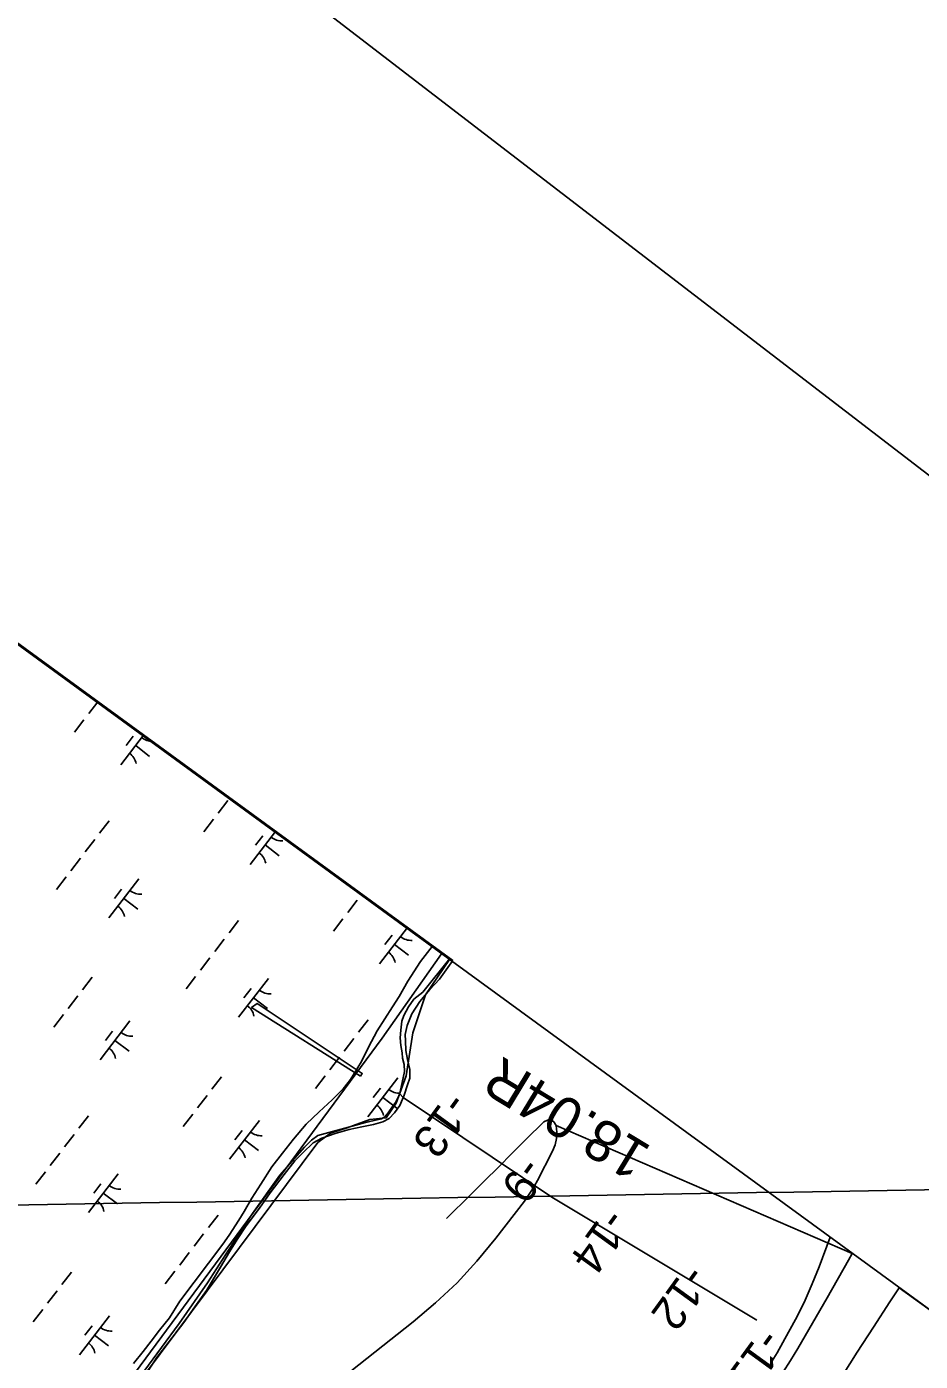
# Model space of a CAD drawing. Extents: x 3879599 to 3900814, y 146526 to 168888.
# Drawn here: x 3894566 to 3895476, y 162574 to 163934 of the extents above; entities that cross this region are included whole.
import ezdxf

# ---------------------------------------------------------------- set-up
doc = ezdxf.new("R2010")
doc.units = 0
for name, color, linetype in [('V-ANNO-SYMB', 7, 'Continuous'), ('V-CHAN-DOCK', 7, 'Continuous'), ('V-GRID-FRAM', 7, 'Continuous'), ('V-GRID-MAJR', 7, 'Continuous'), ('V-LEVE-TOET', 7, 'Continuous'), ('V-RIVR-EDGE', 7, 'Continuous'), ('V-RIVR-JETY', 7, 'Continuous'), ('V-RIVR-RANG', 7, 'Continuous'), ('V-RRAP-FSHR', 7, 'Continuous'), ('V-STRM-FMON', 7, 'Continuous'), ('V-TOPO-DPTH', 7, 'Continuous'), ('V-TOPO-MINR', 7, 'Continuous'), ('V-WETL-SWMP', 7, 'Continuous')]:
    doc.layers.add(name, color=color, linetype=linetype)

msp = doc.modelspace()

# ---------------------------------------------------------------- linework, layer by layer
at = {"layer": 'V-ANNO-SYMB'}
msp.add_lwpolyline([(3890411.2, 167376), (3880331.9, 154259.9), (3889417.3, 147278), (3899496.7, 160394.1), (3890411.2, 167376)], dxfattribs=at)
at = {"layer": 'V-CHAN-DOCK'}
msp.add_lwpolyline([(3894905.9, 162864.7), (3894795.1, 162934.6), (3894800.7, 162938.7), (3894907.9, 162867.4), (3894907.9, 162867.4)], close=True, dxfattribs=at)
at = {"layer": 'V-GRID-FRAM'}
msp.add_lwpolyline([(3898776.6, 160226.4), (3889730.7, 148455.2), (3882888.9, 153284.4), (3891901.5, 165241.3), (3898776.6, 160226.4)], dxfattribs=at)
at = {"layer": 'V-GRID-MAJR'}
msp.add_spline([(3889435.5, 162648.2), (3893979, 162723.9), (3896411.9, 162764.6)], degree=3, dxfattribs=at)
at = {"layer": 'V-LEVE-TOET'}
msp.add_lwpolyline([(3894946.2, 162846.8), (3894949.5, 162843.2), (3895101.1, 162741.4), (3895310, 162616.3)], dxfattribs=at)
at = {"layer": 'V-RIVR-EDGE'}
msp.add_lwpolyline([(3894996.8, 162983.5), (3894972.2, 162947.8), (3894959.2, 162908.8), (3894952.7, 162865.1), (3894942.5, 162837.3), (3894932.3, 162822.4), (3894915.5, 162820.5), (3894892.3, 162812.2), (3894875.6, 162806.6), (3894862.6, 162797.3), (3894686, 162560.4), (3894503, 162313.2), (3894441.7, 162241.6), (3894369.2, 162130.1), (3894334.8, 162095.7), (3894315.3, 162075.3), (3893894.3, 161523.4), (3893644.4, 161210.2), (3893630.5, 161202.8), (3893449.3, 161162.8), (3893262.5, 161121.9), (3892618.5, 160989.1), (3892386.2, 160942.6)], dxfattribs=at)
at = {"layer": 'V-RIVR-JETY'}
for points in [[(3894979.6, 162997.5), (3894979.1, 162996.9), (3894967.3, 162981.5), (3894954.4, 162961.7), (3894945.5, 162945.9), (3894938.7, 162935.5), (3894923.1, 162911.1), (3894914.3, 162894.3), (3894907.2, 162879.8), (3894896, 162861.4), (3894888.5, 162852), (3894877.3, 162840.6), (3894864.1, 162828.6), (3894850.6, 162815.9), (3894837.7, 162800.5), (3894826.6, 162786.4), (3894815.7, 162772.3), (3894804.5, 162754.9), (3894795.4, 162740.4), (3894787.5, 162727), (3894782.1, 162718), (3894772.3, 162702.9), (3894765.8, 162693.8), (3894722.1, 162635.5), (3894711.3, 162618.7), (3894701.1, 162606), (3894692.6, 162594.9), (3894684.5, 162584.2), (3894674.7, 162572.1)], [(3894997.1, 162984.7), (3894969.4, 162950.3), (3894960.5, 162943.1), (3894954.8, 162935.4), (3894950.3, 162926.5), (3894948.2, 162920.9), (3894947, 162911.5), (3894946.5, 162903.9), (3894947.3, 162896.2), (3894948.5, 162888.5), (3894948.8, 162883.2), (3894950.4, 162876.7), (3894950.8, 162869.4), (3894946.6, 162848.8), (3894946.2, 162846.8), (3894942.1, 162838.3), (3894938.8, 162833.8), (3894934.4, 162827.4), (3894930.7, 162823.4), (3894927.4, 162821.4), (3894915.7, 162818.6), (3894905.1, 162815.8), (3894862.6, 162804.3), (3894856.1, 162799.5), (3894853.2, 162796.6), (3894849.1, 162792.6), (3894823.9, 162764), (3894796.1, 162724.9), (3894771.7, 162687.7), (3894750, 162654.3), (3894721.4, 162612.7), (3894685.2, 162563.9)]]:
    msp.add_lwpolyline(points, dxfattribs=at)
at = {"layer": 'V-RRAP-FSHR'}
msp.add_lwpolyline([(3894988.6, 162989.5), (3894928.1, 162903.5), (3894582.9, 162435.8), (3894412.9, 162213.5), (3894350.9, 162125.8), (3894296.7, 162068.7), (3894092.5, 161803.5), (3893724.5, 161331), (3893640.5, 161218.2), (3893416.1, 161165.6), (3892609.1, 161000)], dxfattribs=at)
at = {"layer": 'V-TOPO-DPTH'}
msp.add_line((3895669.6, 162492.7), (3895455, 162649.3), dxfattribs=at)
for points in [[(3894583.4, 161564.9), (3894255.7, 161739.6), (3894330.1, 161816), (3894779.1, 162471.7), (3894959.7, 162614.4), (3894982.6, 162633.9), (3895004.4, 162654.4), (3895024.6, 162676.5), (3895043.8, 162699.7), (3895073, 162737.6), (3895076.7, 162742.7), (3895080.1, 162747.8), (3895083.3, 162753.2), (3895086.4, 162758.6), (3895101.8, 162788.4), (3895104.3, 162794.7), (3895105.9, 162801.2), (3895106.1, 162807.8), (3895105.4, 162814.6), (3895407.1, 162684.2)], [(3895407.1, 162684.2), (3895403.3, 162677.4), (3895381.5, 162638.9), (3895351.7, 162587.4), (3895344.2, 162575), (3895336.4, 162562.9)], [(3895336.4, 162562.9), (3895344.2, 162575), (3895351.7, 162587.4), (3895381.5, 162638.9), (3895403.3, 162677.4), (3895407.1, 162684.2)], [(3895455, 162649.3), (3895445.3, 162634.8), (3895428.6, 162609.2), (3895412.1, 162583.5), (3895389.6, 162547.9)], [(3895455, 162649.3), (3895445.3, 162634.8), (3895428.6, 162609.2), (3895412.1, 162583.5), (3895389.6, 162547.9)]]:
    msp.add_lwpolyline(points, dxfattribs=at)
at = {"layer": 'V-TOPO-MINR'}
for points in [[(3894993.7, 162719.7), (3895018.3, 162744.2), (3895032.4, 162758.2), (3895046.5, 162772.2), (3895060.6, 162786.2), (3895074.6, 162800.2), (3895092.7, 162818.4), (3895096.7, 162820.1), (3895100.2, 162820.3), (3895103.1, 162818.2), (3895105.4, 162814.6), (3895106.1, 162807.8), (3895105.9, 162801.2), (3895104.3, 162794.7), (3895101.8, 162788.4), (3895086.4, 162758.6), (3895083.3, 162753.2), (3895080.1, 162747.8), (3895076.7, 162742.7), (3895073, 162737.6), (3895043.8, 162699.7), (3895024.6, 162676.5), (3895004.4, 162654.4), (3894982.6, 162633.9), (3894959.7, 162614.4), (3894779.1, 162471.7)], [(3895384.6, 162700.7), (3895373.2, 162670.5), (3895366.4, 162653.4), (3895359, 162636.6), (3895350.9, 162620.1), (3895342.2, 162603.9), (3895330.5, 162583), (3895327.2, 162577.4), (3895323.7, 162572)], [(3895407.1, 162684.2), (3895403.3, 162677.4), (3895381.5, 162638.9), (3895351.7, 162587.4), (3895344.2, 162575), (3895336.4, 162562.9)], [(3895455, 162649.3), (3895445.3, 162634.8), (3895428.6, 162609.2), (3895412.1, 162583.5), (3895389.6, 162547.9)]]:
    msp.add_lwpolyline(points, dxfattribs=at)
at = {"layer": 'V-WETL-SWMP'}
for p, q in [((3895000.1, 162982.5), (3893763.6, 163884.4)), ((3894638.5, 163246.3), (3894629.2, 163234.2)), ((3894624.3, 163227.8), (3894614.6, 163215.1)), ((3894685.1, 163212.3), (3894661.7, 163181.8)), ((3894674.5, 163211.1), (3894667.2, 163201.6)), ((3894677, 163201.6), (3894691.2, 163190.6)), ((3894770.8, 163145.5), (3894761.1, 163132.8)), ((3894650, 163124.9), (3894640.2, 163112.2)), ((3894756.2, 163126.5), (3894746.5, 163113.8)), ((3894819.6, 163114.2), (3894793.6, 163080.4)), ((3894806.4, 163109.7), (3894799.1, 163100.2)), ((3894635.4, 163105.8), (3894625.6, 163093.2)), ((3894808.9, 163100.3), (3894823.1, 163089.3)), ((3894620.7, 163086.8), (3894611, 163074.1)), ((3894606.1, 163067.8), (3894596.4, 163055.1)), ((3894680.3, 163065.8), (3894649.8, 163026.1)), ((3894662.6, 163055.4), (3894655.3, 163045.9)), ((3894665, 163045.9), (3894679.3, 163035)), ((3894902.7, 163044.1), (3894893, 163031.5)), ((3894888.1, 163025.1), (3894878.4, 163012.4)), ((3894781.9, 163023.5), (3894772.1, 163010.8)), ((3894954, 163016.1), (3894925.5, 162979.1)), ((3894767.3, 163004.5), (3894757.5, 162991.8)), ((3894938.3, 163008.4), (3894931, 162998.9)), ((3894940.8, 162998.9), (3894955, 162987.9)), ((3894752.6, 162985.5), (3894742.9, 162972.8)), ((3894986.4, 162963.5), (3895000.1, 162982.5)), ((3894632.5, 162965.5), (3894622.8, 162952.9)), ((3894738, 162966.4), (3894728.3, 162953.7)), ((3894812.2, 162964.4), (3894781.7, 162924.8)), ((3894976.6, 162953), (3894986.4, 162963.5)), ((3894617.9, 162946.5), (3894608.2, 162933.8)), ((3894794.5, 162954), (3894787.2, 162944.5)), ((3894796.9, 162944.6), (3894811.2, 162933.6)), ((3894966.4, 162940.9), (3894976.6, 162953)), ((3894958.2, 162928.4), (3894966.4, 162940.9)), ((3894603.3, 162927.5), (3894593.6, 162914.8)), ((3894671.2, 162921.1), (3894640.7, 162881.5)), ((3894913.8, 162922.2), (3894904, 162909.5)), ((3894951.6, 162907.4), (3894953.7, 162916.3)), ((3894953.7, 162916.3), (3894958.2, 162928.4)), ((3894653.5, 162910.7), (3894646.2, 162901.2)), ((3894899.1, 162903.1), (3894889.4, 162890.4)), ((3894952, 162900.9), (3894951.6, 162907.4)), ((3894655.9, 162901.3), (3894670.2, 162890.3)), ((3894952.4, 162890.8), (3894952, 162900.9)), ((3894953.9, 162881.9), (3894952.4, 162890.8)), ((3894884.5, 162884.1), (3894874.8, 162871.4)), ((3894956.3, 162871.7), (3894953.9, 162881.9)), ((3894764.4, 162864.2), (3894754.7, 162851.5)), ((3894869.9, 162865.1), (3894860.2, 162852.4)), ((3894944.1, 162863), (3894913.6, 162823.4)), ((3894953.8, 162855.9), (3894956.3, 162862.8)), ((3894956.3, 162862.8), (3894956.3, 162871.7)), ((3894926.4, 162852.7), (3894919, 162843.2)), ((3894950.5, 162845.4), (3894953.8, 162855.9)), ((3894749.8, 162845.2), (3894740.1, 162832.5)), ((3894928.8, 162843.2), (3894943.1, 162832.3)), ((3894940.7, 162827.3), (3894946, 162834.9)), ((3894946, 162834.9), (3894950.5, 162845.4)), ((3894629, 162824.5), (3894619.2, 162811.8)), ((3894735.2, 162826.1), (3894725.4, 162813.4)), ((3894928.9, 162818.4), (3894935.4, 162821.6)), ((3894935.4, 162821.6), (3894940.7, 162827.3)), ((3894803.1, 162819.7), (3894772.6, 162780.1)), ((3894785.4, 162809.4), (3894778.1, 162799.9)), ((3894880.2, 162806.5), (3894894.4, 162810.5)), ((3894894.4, 162810.5), (3894907.4, 162813.3)), ((3894907.4, 162813.3), (3894919.2, 162815.6)), ((3894919.2, 162815.6), (3894928.9, 162818.4)), ((3894614.3, 162805.5), (3894604.6, 162792.8)), ((3894787.8, 162799.9), (3894802.1, 162789)), ((3894847.3, 162786.8), (3894857.9, 162796.9)), ((3894857.9, 162796.9), (3894866.8, 162801.7)), ((3894866.8, 162801.7), (3894880.2, 162806.5)), ((3894599.7, 162786.5), (3894590, 162773.8)), ((3894839.2, 162778.4), (3894847.3, 162786.8)), ((3894585.1, 162767.4), (3894575.3, 162754.8)), ((3894828.2, 162764.7), (3894839.2, 162778.4)), ((3894659.3, 162765.4), (3894628.8, 162725.8)), ((3894641.6, 162755), (3894634.2, 162745.5)), ((3894813.9, 162746.1), (3894828.2, 162764.7)), ((3894644, 162745.6), (3894658.3, 162734.6)), ((3894803.3, 162730.4), (3894813.9, 162746.1)), ((3894789.4, 162712.2), (3894803.3, 162730.4)), ((3894760.9, 162723.2), (3894751.1, 162710.5)), ((3894780.4, 162698.5), (3894789.4, 162712.2)), ((3894746.2, 162704.1), (3894736.5, 162691.5)), ((3894772.7, 162686), (3894780.4, 162698.5)), ((3894731.6, 162685.1), (3894721.9, 162672.4)), ((3894763.3, 162670.2), (3894772.7, 162686)), ((3894611.5, 162665.2), (3894601.8, 162652.5)), ((3894717, 162666.1), (3894707.2, 162653.4)), ((3894749, 162646.4), (3894763.3, 162670.2)), ((3894596.9, 162646.2), (3894587.2, 162633.5)), ((3894737.1, 162629.9), (3894749, 162646.4)), ((3894582.3, 162627.1), (3894572.5, 162614.5)), ((3894650.2, 162620.8), (3894619.7, 162581.1)), ((3894726.1, 162613.7), (3894737.1, 162629.9)), ((3894632.5, 162610.4), (3894625.2, 162600.9)), ((3894713.5, 162597.6), (3894726.1, 162613.7)), ((3894634.9, 162600.9), (3894649.2, 162590)), ((3894698.4, 162578.2), (3894713.5, 162597.6)), ((3894688.2, 162562.5), (3894698.4, 162578.2))]:
    msp.add_line(p, q, dxfattribs=at)
for centre, start, end in [((3894694, 163223.4), 231.6869, 270.2397), ((3894660.3, 163179.6), 11.6869, 53.2305), ((3894825.9, 163122), 231.6869, 273.2305), ((3894792.2, 163078.2), 11.6869, 53.2305), ((3894682.1, 163067.7), 231.6869, 273.2305), ((3894648.4, 163023.9), 11.6869, 53.2305), ((3894957.8, 163020.7), 231.6869, 273.2305), ((3894924.1, 162976.9), 11.6869, 53.2305), ((3894814, 162966.3), 231.6869, 273.2305), ((3894780.3, 162922.5), 11.6869, 53.2305), ((3894673, 162923), 231.6869, 273.2305), ((3894639.3, 162879.2), 11.6869, 53.2305), ((3894945.8, 162865), 231.6869, 273.2305), ((3894912.2, 162821.2), 11.6869, 53.2305), ((3894804.9, 162821.7), 231.6869, 273.2305), ((3894771.2, 162777.9), 11.6869, 53.2305), ((3894661, 162767.3), 231.6869, 273.2305), ((3894627.4, 162723.5), 11.6869, 53.2305), ((3894651.9, 162622.7), 231.6869, 273.2305), ((3894618.3, 162578.9), 11.6869, 53.2305)]:
    msp.add_arc(centre, 17.6, start, end, dxfattribs=at)

# ---------------------------------------------------------------- texts
at = {"layer": 'V-RIVR-RANG'}
for s, p in [('-13', (3894995.7, 162850.6)), ('-9', (3895071.3, 162784.5)), ('-14', (3895156.9, 162732.2)), ('-12', (3895238.8, 162674.9)), ('-11', (3895315, 162609.6))]:
    msp.add_text(s, height=33.5, rotation=234.0383, dxfattribs=at).set_placement(p)
at = {"layer": 'V-STRM-FMON'}
msp.add_text('18.04R', height=42, rotation=148.7867, dxfattribs=at).set_placement((3895204, 162792.2))

doc.saveas('drawing.dxf')
